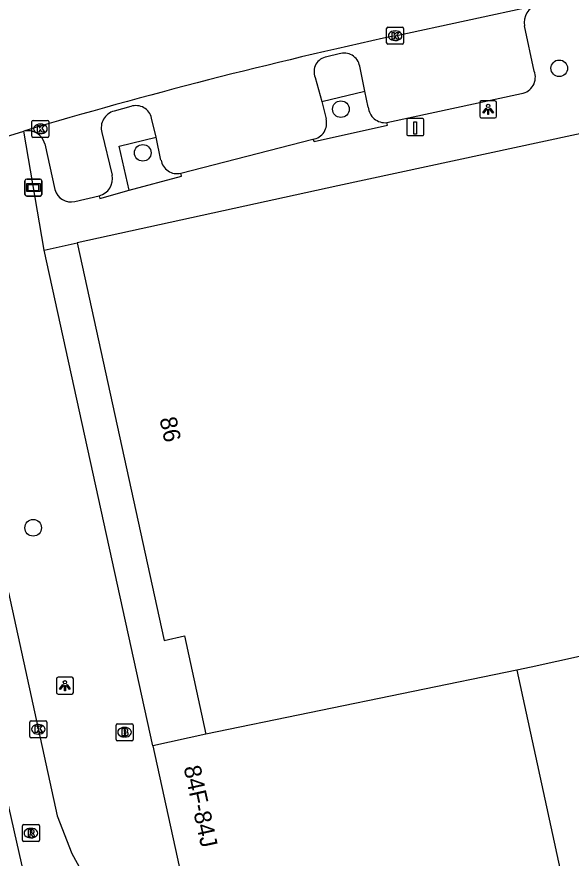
# Model space of a CAD drawing. Extents: x 160557 to 161245, y 385330 to 386505.
# Drawn here: x 160747.84 to 160780.49, y 385859.79 to 385909.32 of the extents above; entities that cross this region are included whole.
import ezdxf

# ---------------------------------------------------------------- set-up
doc = ezdxf.new("R2010")
doc.units = 0
for name, color, linetype in [('IMGEO_Boom', 7, 'Continuous'), ('IMGEO_Brandkraan', 7, 'Continuous'), ('IMGEO_Fietspad_gesloten', 7, 'Continuous'), ('IMGEO_Kolk', 7, 'Continuous'), ('IMGEO_Laadpaal', 7, 'Continuous'), ('IMGEO_Lichtpunt', 7, 'Continuous'), ('IMGEO_Pand', 7, 'Continuous'), ('IMGEO_Pand_nummerreeks', 7, 'Continuous'), ('IMGEO_Parkeervlak_open', 7, 'Continuous'), ('IMGEO_Reclamebord', 7, 'Continuous'), ('IMGEO_Rijbaan_lokaal_gesloten', 7, 'Continuous'), ('IMGEO_Rioolput', 7, 'Continuous'), ('IMGEO_Verkeerseiland_open', 7, 'Continuous'), ('IMGEO_Voetpad_open', 7, 'Continuous')]:
    doc.layers.add(name, color=color, linetype=linetype)

msp = doc.modelspace()

# ---------------------------------------------------------------- linework, layer by layer
at = {"layer": 'IMGEO_Boom'}
for centre in [(160779.781, 385906.285), (160766.921, 385903.88), (160755.254, 385901.31), (160748.797, 385879.235)]:
    msp.add_circle(centre, 0.489, dxfattribs=at)
at = {"layer": 'IMGEO_Brandkraan'}
for p, q in [((160753.681, 385866.773), (160753.681, 385867.625)), ((160753.756, 385867.699), (160754.608, 385867.699)), ((160754.169, 385867.479), (160754.194, 385867.479)), ((160754.682, 385867.625), (160754.682, 385866.773)), ((160754.192, 385866.919), (160754.167, 385866.919)), ((160754.608, 385866.699), (160753.756, 385866.699))]:
    msp.add_line(p, q, dxfattribs=at)
for points in [[(160753.681, 385866.773), (160753.681, 385867.625)], [(160753.756, 385867.699), (160754.608, 385867.699)], [(160754.029, 385867.399), (160754.029, 385866.999), (160754.242, 385866.999)], [(160754.26, 385867.399), (160754.029, 385867.399)], [(160754.682, 385867.625), (160754.682, 385866.773)], [(160754.208, 385867.318), (160754.154, 385867.318), (160754.154, 385867.242)], [(160754.154, 385867.242), (160754.207, 385867.242)], [(160754.216, 385867.166), (160754.154, 385867.166), (160754.154, 385867.085)], [(160754.154, 385867.085), (160754.216, 385867.085)], [(160754.608, 385866.699), (160753.756, 385866.699)]]:
    msp.add_lwpolyline(points, dxfattribs=at)
for centre, radius, start, end in [((160753.758, 385867.623), 0.0765, 91.552, 178.448), ((160753.758, 385867.623), 0.0765, 91.552, 178.448), ((160754.264, 385867.254), 0.145, 59.4692, 91.5367), ((160754.289, 385867.301), 0.0922, 285.5137, 58.1501), ((160754.606, 385867.623), 0.0765, 1.552, 88.448), ((160754.606, 385867.623), 0.0765, 1.552, 88.448), ((160754.209, 385867.28), 0.0379, 267.8285, 90.9355), ((160754.217, 385867.125), 0.0404, 269.8759, 90.5077), ((160754.248, 385867.25), 0.251, 268.6676, 293.5347), ((160754.294, 385867.109), 0.105, 301.3115, 78.989), ((160753.758, 385866.775), 0.0765, 181.552, 268.448), ((160753.758, 385866.775), 0.0765, 181.552, 268.448), ((160754.606, 385866.775), 0.0765, 271.552, 358.448), ((160754.606, 385866.775), 0.0765, 271.552, 358.448)]:
    msp.add_arc(centre, radius, start, end, dxfattribs=at)
for centre, major_axis, ratio, start_param, end_param in [((160754.168, 385867.199), (-0.387, 0.002), 0.722429, 4.712389, 7.853982), ((160754.193, 385867.199), (-0.39, 0.002), 0.717154, 1.570796, 4.712389)]:
    msp.add_ellipse(centre, major_axis=major_axis, ratio=ratio, start_param=start_param, end_param=end_param, dxfattribs=at)
at = {"layer": 'IMGEO_Fietspad_gesloten'}
for points in [[(160747.348, 385875.432), (160750.213, 385862.278), (160751.082, 385860.062), (160752.047, 385858.308)], [(160775.118, 385735.103), (160749.654, 385852.647), (160746.978, 385864.559), (160746.687, 385864.512)]]:
    msp.add_lwpolyline(points, dxfattribs=at)
at = {"layer": 'IMGEO_Kolk'}
for p, q in [((160769.617, 385907.776), (160769.617, 385908.628)), ((160769.692, 385908.702), (160770.544, 385908.702)), ((160770.105, 385908.482), (160770.13, 385908.482)), ((160770.618, 385908.628), (160770.618, 385907.776)), ((160770.544, 385907.702), (160769.692, 385907.702)), ((160770.128, 385907.922), (160770.103, 385907.922)), ((160748.725, 385902.294), (160748.725, 385903.146)), ((160748.8, 385903.22), (160749.652, 385903.22)), ((160749.213, 385903), (160749.238, 385903)), ((160749.726, 385903.146), (160749.726, 385902.294)), ((160749.652, 385902.22), (160748.8, 385902.22)), ((160749.236, 385902.44), (160749.211, 385902.44)), ((160748.677, 385867.875), (160749.529, 385867.875)), ((160748.602, 385866.949), (160748.602, 385867.801)), ((160749.09, 385867.655), (160749.115, 385867.655)), ((160749.603, 385867.801), (160749.603, 385866.949)), ((160749.529, 385866.875), (160748.677, 385866.875)), ((160749.113, 385867.095), (160749.088, 385867.095))]:
    msp.add_line(p, q, dxfattribs=at)
for points in [[(160769.617, 385907.776), (160769.617, 385908.628)], [(160769.692, 385908.702), (160770.544, 385908.702)], [(160770.618, 385908.628), (160770.618, 385907.776)], [(160769.938, 385908.402), (160770.061, 385908.402), (160770.061, 385908.251), (160770.191, 385908.402), (160770.355, 385908.402), (160770.209, 385908.251), (160770.362, 385908.002), (160770.21, 385908.002), (160770.125, 385908.166), (160770.061, 385908.099), (160770.061, 385908.002), (160769.938, 385908.002), (160769.938, 385908.402)], [(160770.544, 385907.702), (160769.692, 385907.702)], [(160748.725, 385902.294), (160748.725, 385903.146)], [(160748.8, 385903.22), (160749.652, 385903.22)], [(160749.726, 385903.146), (160749.726, 385902.294)], [(160749.046, 385902.92), (160749.169, 385902.92), (160749.169, 385902.769), (160749.299, 385902.92), (160749.463, 385902.92), (160749.317, 385902.769), (160749.47, 385902.52), (160749.318, 385902.52), (160749.233, 385902.684), (160749.169, 385902.617), (160749.169, 385902.52), (160749.046, 385902.52), (160749.046, 385902.92)], [(160749.652, 385902.22), (160748.8, 385902.22)], [(160748.677, 385867.875), (160749.529, 385867.875)], [(160748.602, 385866.949), (160748.602, 385867.801)], [(160748.923, 385867.575), (160749.046, 385867.575), (160749.046, 385867.424), (160749.176, 385867.575), (160749.34, 385867.575), (160749.194, 385867.424), (160749.347, 385867.175), (160749.195, 385867.175), (160749.11, 385867.339), (160749.046, 385867.272), (160749.046, 385867.175), (160748.923, 385867.175), (160748.923, 385867.575)], [(160749.603, 385867.801), (160749.603, 385866.949)], [(160749.529, 385866.875), (160748.677, 385866.875)]]:
    msp.add_lwpolyline(points, dxfattribs=at)
for centre, start, end in [((160769.694, 385908.626), 91.552, 178.448), ((160769.694, 385908.626), 91.552, 178.448), ((160770.542, 385908.626), 1.552, 88.448), ((160770.542, 385908.626), 1.552, 88.448), ((160769.694, 385907.778), 181.552, 268.448), ((160769.694, 385907.778), 181.552, 268.448), ((160770.542, 385907.778), 271.552, 358.448), ((160770.542, 385907.778), 271.552, 358.448), ((160748.802, 385903.144), 91.552, 178.448), ((160748.802, 385903.144), 91.552, 178.448), ((160749.65, 385903.144), 1.552, 88.448), ((160749.65, 385903.144), 1.552, 88.448), ((160748.802, 385902.296), 181.552, 268.448), ((160748.802, 385902.296), 181.552, 268.448), ((160749.65, 385902.296), 271.552, 358.448), ((160749.65, 385902.296), 271.552, 358.448), ((160748.679, 385867.799), 91.552, 178.448), ((160748.679, 385867.799), 91.552, 178.448), ((160749.527, 385867.799), 1.552, 88.448), ((160749.527, 385867.799), 1.552, 88.448), ((160748.679, 385866.951), 181.552, 268.448), ((160748.679, 385866.951), 181.552, 268.448), ((160749.527, 385866.951), 271.552, 358.448), ((160749.527, 385866.951), 271.552, 358.448)]:
    msp.add_arc(centre, 0.0765, start, end, dxfattribs=at)
for centre, major_axis, ratio, start_param, end_param in [((160770.104, 385908.202), (-0.387, 0.002), 0.722429, 4.712389, 7.853982), ((160770.129, 385908.202), (-0.39, 0.002), 0.717154, 1.570796, 4.712389), ((160749.212, 385902.72), (-0.387, 0.002), 0.722429, 4.712389, 7.853982), ((160749.237, 385902.72), (-0.39, 0.002), 0.717154, 1.570796, 4.712389), ((160749.089, 385867.375), (-0.387, 0.002), 0.722429, 4.712389, 7.853982), ((160749.114, 385867.375), (-0.39, 0.002), 0.717154, 1.570796, 4.712389)]:
    msp.add_ellipse(centre, major_axis=major_axis, ratio=ratio, start_param=start_param, end_param=end_param, dxfattribs=at)
at = {"layer": 'IMGEO_Laadpaal'}
for p, q in [((160770.804, 385903.242), (160770.804, 385902.401)), ((160770.804, 385903.242), (160770.804, 385902.401)), ((160771.72, 385903.326), (160770.879, 385903.326)), ((160771.72, 385903.326), (160770.879, 385903.326)), ((160771.804, 385902.41), (160771.804, 385903.251)), ((160771.804, 385902.41), (160771.804, 385903.251)), ((160770.888, 385902.326), (160771.729, 385902.326)), ((160770.888, 385902.326), (160771.729, 385902.326))]:
    msp.add_line(p, q, dxfattribs=at)
msp.add_lwpolyline([(160771.219, 385903.139), (160771.379, 385903.139), (160771.379, 385902.406), (160771.219, 385902.406), (160771.219, 385903.139)], dxfattribs=at)
for centre, start, end in [((160770.882, 385903.248), 92.4484, 184.2845), ((160770.882, 385903.248), 92.4484, 184.2845), ((160771.726, 385903.248), 2.4484, 94.2845), ((160771.726, 385903.248), 2.4484, 94.2845), ((160770.882, 385902.404), 182.4484, 274.2845), ((160770.882, 385902.404), 182.4484, 274.2845), ((160771.726, 385902.404), 272.4484, 4.2845), ((160771.726, 385902.404), 272.4484, 4.2845)]:
    msp.add_arc(centre, 0.0779, start, end, dxfattribs=at)
at = {"layer": 'IMGEO_Lichtpunt'}
for p, q in [((160775.096, 385904.273), (160775.096, 385903.466)), ((160775.096, 385904.273), (160775.096, 385903.466)), ((160775.998, 385904.368), (160775.19, 385904.368)), ((160775.998, 385904.368), (160775.19, 385904.368)), ((160776.092, 385903.466), (160776.092, 385904.273)), ((160776.092, 385903.466), (160776.092, 385904.273)), ((160775.19, 385903.372), (160775.998, 385903.372)), ((160775.19, 385903.372), (160775.998, 385903.372)), ((160750.172, 385870.344), (160750.172, 385869.537)), ((160750.172, 385870.344), (160750.172, 385869.537)), ((160751.074, 385870.439), (160750.266, 385870.439)), ((160751.074, 385870.439), (160750.266, 385870.439)), ((160751.168, 385869.537), (160751.168, 385870.344)), ((160751.168, 385869.537), (160751.168, 385870.344)), ((160750.266, 385869.443), (160751.074, 385869.443)), ((160750.266, 385869.443), (160751.074, 385869.443))]:
    msp.add_line(p, q, dxfattribs=at)
for points in [[(160775.47, 385903.937), (160775.509, 385903.909), (160775.321, 385903.647), (160775.283, 385903.674), (160775.47, 385903.937)], [(160775.572, 385903.889), (160775.619, 385903.889), (160775.619, 385903.567), (160775.572, 385903.567), (160775.572, 385903.889)], [(160775.682, 385903.909), (160775.72, 385903.936), (160775.907, 385903.674), (160775.868, 385903.646), (160775.682, 385903.909)], [(160750.546, 385870.008), (160750.585, 385869.98), (160750.397, 385869.718), (160750.359, 385869.745), (160750.546, 385870.008)], [(160750.648, 385869.96), (160750.695, 385869.96), (160750.695, 385869.638), (160750.648, 385869.638), (160750.648, 385869.96)], [(160750.758, 385869.98), (160750.796, 385870.007), (160750.983, 385869.745), (160750.944, 385869.717), (160750.758, 385869.98)]]:
    msp.add_lwpolyline(points, dxfattribs=at)
for centre in [(160775.595, 385904.071), (160750.671, 385870.142)]:
    msp.add_circle(centre, 0.0994, dxfattribs=at)
for centre, start, end in [((160775.19, 385904.273), 90, 180), ((160775.19, 385904.273), 90, 180), ((160775.998, 385904.273), 0, 90), ((160775.998, 385904.273), 0, 90), ((160775.19, 385903.466), 180, 270), ((160775.19, 385903.466), 180, 270), ((160775.998, 385903.466), 270, 0), ((160775.998, 385903.466), 270, 360), ((160750.266, 385870.344), 90, 180), ((160750.266, 385870.344), 90, 180), ((160751.074, 385870.344), 0, 90), ((160751.074, 385870.344), 0, 90), ((160750.266, 385869.537), 180, 270), ((160750.266, 385869.537), 180, 270), ((160751.074, 385869.537), 270, 0), ((160751.074, 385869.537), 270, 360)]:
    msp.add_arc(centre, 0.0946, start, end, dxfattribs=at)
at = {"layer": 'IMGEO_Pand'}
for points in [[(160782.353, 385902.729), (160766.738, 385899.37), (160751.387, 385896.009)], [(160751.387, 385896.009), (160756.51, 385872.607), (160757.708, 385872.869), (160758.975, 385867.079)], [(160790.054, 385873.952), (160789.8, 385873.897), (160789.862, 385873.612), (160778.133, 385871.025), (160777.279, 385870.849)], [(160777.279, 385870.849), (160758.975, 385867.079)], [(160777.279, 385870.849), (160779.843, 385859.099)], [(160758.975, 385867.079), (160755.843, 385866.393)], [(160755.843, 385866.393), (160757.924, 385856.888), (160759.385, 385857.208), (160759.667, 385855.919), (160758.206, 385855.6), (160758.439, 385854.537)]]:
    msp.add_lwpolyline(points, dxfattribs=at)
at = {"layer": 'IMGEO_Parkeervlak_open'}
for points in [[(160766.813, 385907.137), (160766.092, 385906.959)], [(160768.335, 385904.934), (160768.032, 385906.413)], [(160765.407, 385905.752), (160765.795, 385904.338)], [(160768.535, 385904.001), (160768.335, 385904.934)], [(160754.558, 385904.043), (160753.565, 385903.771)], [(160765.795, 385904.338), (160766.048, 385903.309)], [(160756.035, 385902.233), (160755.776, 385903.353)], [(160752.846, 385902.51), (160753.451, 385900.002)], [(160756.327, 385900.886), (160756.035, 385902.233)]]:
    msp.add_lwpolyline(points, dxfattribs=at)
for centre, radius, start, end in [((160766.215, 385906.091), 0.876, 98.0792, 202.769), ((160767.104, 385906.239), 0.944, 10.5968, 107.9885), ((160754.851, 385903.14), 0.949, 12.9511, 107.9856), ((160769.52, 385904.071), 0.987, 184.0779, 275.8764), ((160753.825, 385902.787), 1.018, 104.8129, 195.8051), ((160765.136, 385903.045), 0.949, 278.2122, 16.1394), ((160757.274, 385901.042), 0.959, 189.3354, 283.3297), ((160752.418, 385899.797), 1.053, 284.3589, 11.2025)]:
    msp.add_arc(centre, radius, start, end, dxfattribs=at)
at = {"layer": 'IMGEO_Reclamebord'}
for p, q in [((160748.317, 385898.865), (160748.317, 385899.665)), ((160748.317, 385899.665), (160748.317, 385898.865)), ((160748.417, 385899.765), (160749.207, 385899.765)), ((160749.207, 385899.765), (160748.417, 385899.765)), ((160749.307, 385899.665), (160749.307, 385898.865)), ((160749.307, 385898.865), (160749.307, 385899.665)), ((160749.207, 385898.765), (160748.417, 385898.765)), ((160748.417, 385898.765), (160749.207, 385898.765))]:
    msp.add_line(p, q, dxfattribs=at)
for points in [[(160748.418, 385899.497), (160749.206, 385899.497), (160749.206, 385899.033), (160748.418, 385899.033), (160748.418, 385899.497)], [(160748.483, 385899.432), (160748.483, 385899.098), (160749.141, 385899.098), (160749.141, 385899.432), (160748.483, 385899.432)]]:
    msp.add_lwpolyline(points, dxfattribs=at)
for centre, start, end in [((160748.417, 385899.665), 90, 180), ((160748.417, 385899.665), 90, 180), ((160749.207, 385899.665), 0, 90), ((160749.207, 385899.665), 360, 90), ((160748.417, 385898.865), 180, 270), ((160748.417, 385898.865), 180, 270), ((160749.207, 385898.865), 270, 0), ((160749.207, 385898.865), 270, 0)]:
    msp.add_arc(centre, 0.1, start, end, dxfattribs=at)
at = {"layer": 'IMGEO_Rijbaan_lokaal_gesloten'}
for points in [[(160770.117, 385908.203), (160778.483, 385910.006)], [(160746.075, 385901.918), (160748.25, 385902.591)]]:
    msp.add_lwpolyline(points, dxfattribs=at)
msp.add_arc((160833.654, 385615.226), 299.787, 102.23602, 106.55173, dxfattribs=at)
at = {"layer": 'IMGEO_Rioolput'}
for p, q in [((160748.164, 385860.836), (160748.164, 385861.688)), ((160748.239, 385861.762), (160749.091, 385861.762)), ((160748.652, 385861.542), (160748.677, 385861.542)), ((160749.165, 385861.688), (160749.165, 385860.836)), ((160748.675, 385860.982), (160748.65, 385860.982)), ((160749.091, 385860.762), (160748.239, 385860.762))]:
    msp.add_line(p, q, dxfattribs=at)
for points in [[(160748.164, 385860.836), (160748.164, 385861.688)], [(160748.239, 385861.762), (160749.091, 385861.762)], [(160748.753, 385861.46), (160748.501, 385861.462), (160748.501, 385861.062)], [(160749.165, 385861.688), (160749.165, 385860.836)], [(160748.501, 385861.062), (160748.625, 385861.062), (160748.625, 385861.224), (160748.636, 385861.224)], [(160748.679, 385861.381), (160748.625, 385861.381), (160748.625, 385861.3)], [(160748.625, 385861.3), (160748.677, 385861.3)], [(160748.683, 385861.195), (160748.754, 385861.062), (160748.894, 385861.062), (160748.829, 385861.188)], [(160749.091, 385860.762), (160748.239, 385860.762)]]:
    msp.add_lwpolyline(points, dxfattribs=at)
for centre, radius, start, end in [((160748.241, 385861.686), 0.0765, 91.552, 178.448), ((160748.241, 385861.686), 0.0765, 91.552, 178.448), ((160748.752, 385861.35), 0.109, 350.3612, 89.416), ((160749.089, 385861.686), 0.0765, 1.552, 88.448), ((160749.089, 385861.686), 0.0765, 1.552, 88.448), ((160748.635, 385861.171), 0.0533, 26.0293, 88.6989), ((160748.661, 385861.489), 0.19, 274.7715, 282.9687), ((160748.685, 385861.285), 0.0964, 77.0061, 93.1865), ((160748.699, 385861.342), 0.0378, 276.6634, 79.6772), ((160748.75, 385861.35), 0.112, 277.5842, 350.9817), ((160748.734, 385861.135), 0.108, 29.5134, 73.7905), ((160748.241, 385860.838), 0.0765, 181.552, 268.448), ((160748.241, 385860.838), 0.0765, 181.552, 268.448), ((160749.089, 385860.838), 0.0765, 271.552, 358.448), ((160749.089, 385860.838), 0.0765, 271.552, 358.448)]:
    msp.add_arc(centre, radius, start, end, dxfattribs=at)
for centre, major_axis, ratio, start_param, end_param in [((160748.651, 385861.262), (-0.387, 0.002), 0.722429, 4.712389, 7.853982), ((160748.676, 385861.262), (-0.39, 0.002), 0.717154, 1.570796, 4.712389)]:
    msp.add_ellipse(centre, major_axis=major_axis, ratio=ratio, start_param=start_param, end_param=end_param, dxfattribs=at)
at = {"layer": 'IMGEO_Verkeerseiland_open'}
for points in [[(160765.795, 385904.338), (160768.335, 385904.934)], [(160754.45, 385899.114), (160753.854, 385901.703), (160756.035, 385902.233)]]:
    msp.add_lwpolyline(points, dxfattribs=at)
at = {"layer": 'IMGEO_Voetpad_open'}
for points in [[(160778.307, 385906.116), (160777.745, 385908.791)], [(160769.621, 385903.089), (160777.556, 385904.803)], [(160765.272, 385902.106), (160765.351, 385901.973), (160769.666, 385902.929), (160769.621, 385903.089)], [(160749.452, 385895.585), (160748.25, 385902.591)], [(160757.495, 385900.108), (160765.272, 385902.106)], [(160749.488, 385901.848), (160750.074, 385899.143)], [(160754.45, 385899.114), (160757.537, 385899.93), (160757.495, 385900.108)], [(160752.679, 385898.777), (160752.73, 385898.625), (160754.45, 385899.114)], [(160751.251, 385898.437), (160752.679, 385898.777)], [(160749.452, 385895.585), (160751.387, 385896.009)], [(160755.843, 385866.393), (160749.452, 385895.585)]]:
    msp.add_lwpolyline(points, dxfattribs=at)
for centre, radius, start, end in [((160778.745, 385909.015), 1.025, 104.8202, 192.6302), ((160777.408, 385905.759), 0.967, 278.7863, 21.6769), ((160748.463, 385901.543), 1.07, 16.5882, 101.4707), ((160751.046, 385899.429), 1.013, 196.3842, 281.7026)]:
    msp.add_arc(centre, radius, start, end, dxfattribs=at)

# ---------------------------------------------------------------- texts
at = {"layer": 'IMGEO_Pand_nummerreeks'}
for s, p in [('86', (160756.233, 385885.654)), ('84F-84J', (160757.654, 385865.134))]:
    msp.add_text(s, height=1, rotation=282.347, dxfattribs=at).set_placement(p)

doc.saveas('drawing.dxf')
